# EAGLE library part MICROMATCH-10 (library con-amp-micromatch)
MicroMaTch 10 8-215464-0 / 1-215464-0 Drawing Number C-215464 DDEController.pdf
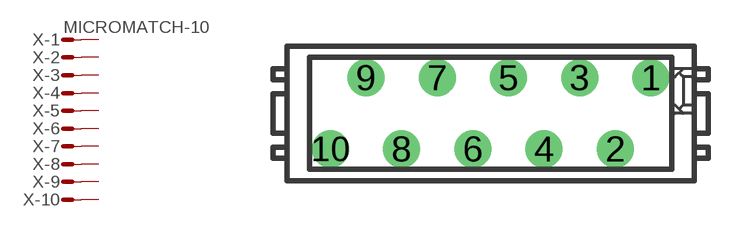
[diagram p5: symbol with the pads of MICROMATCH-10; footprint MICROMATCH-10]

Designator prefix X; gates -1=MV -2=M -3=M -4=M -5=M -6=M -7=M -8=M -9=M -10=M

## MICROMATCH-10 (MF: FARNELL; MPN: 8-215464-0; OC_FARNELL: 3784654; OC_NEWARK: 19J6430)  [MICROMATCH-10]
1  -1:S  pas
2  -2:S  pas
3  -3:S  pas
4  -4:S  pas
5  -5:S  pas
6  -6:S  pas
7  -7:S  pas
8  -8:S  pas
9  -9:S  pas
10  -10:S  pas

## Footprint MICROMATCH-10 (pad centres in mm)
MicroMaTch 10 8-215464-0 / 1-215464-0 Drawing Number C-215464 DDEController.pdf
drill 0.813 round: 1 5.715,1.27; 2 4.445,-1.27; 3 3.175,1.27; 4 1.905,-1.27; 5 0.635,1.27; 6 -0.635,-1.27; 7 -1.905,1.27; 8 -3.175,-1.27; 9 -4.445,1.27; 10 -5.715,-1.27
